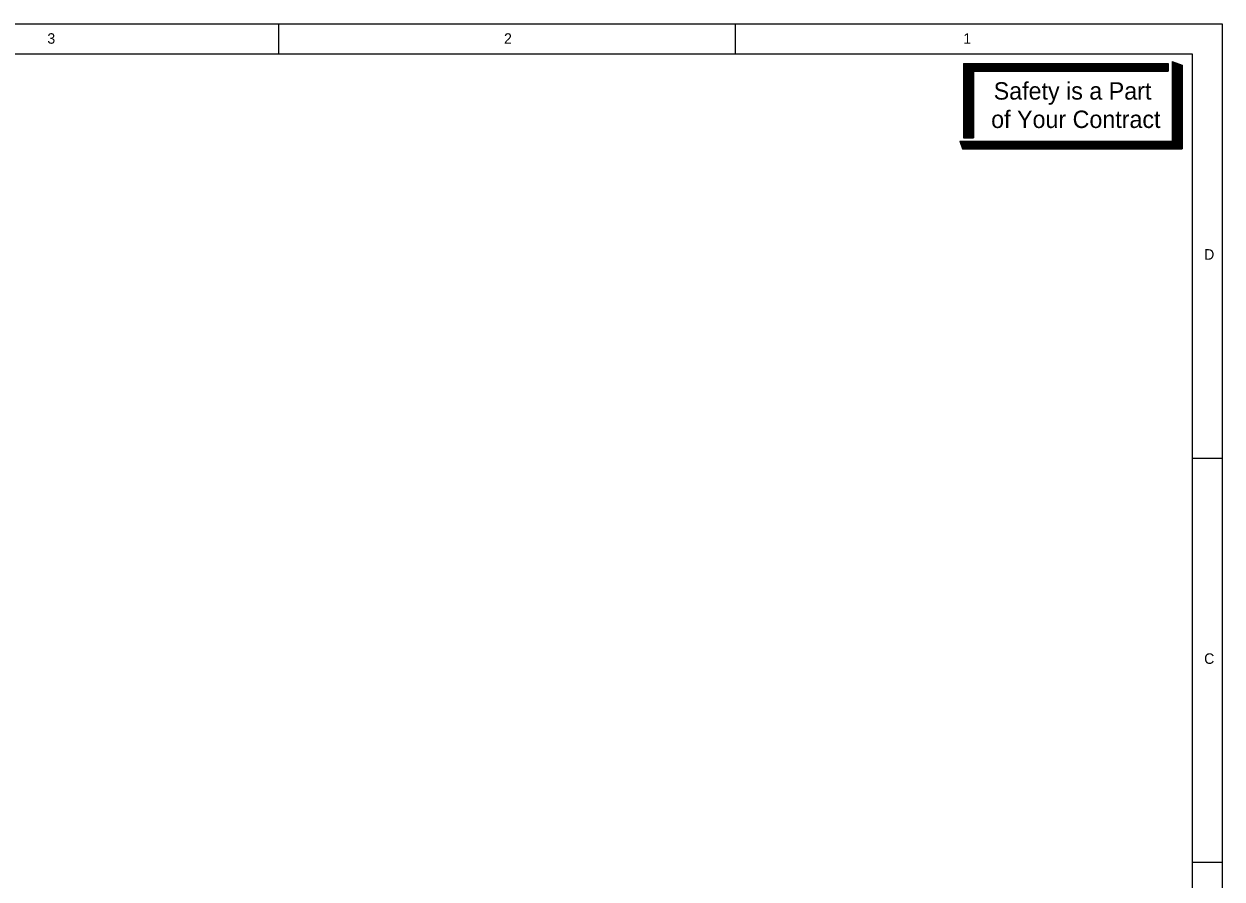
# Model space of a CAD drawing. Extents: x 0 to 320, y -4 to 473.
# Drawn here: x 280.44 to 320.45, y 444.86 to 473.42 of the extents above; entities that cross this region are included whole.
import ezdxf

# ---------------------------------------------------------------- set-up
doc = ezdxf.new("R2010")
doc.units = 0
doc.layers.add('Level 1', color=7, linetype='Continuous')

msp = doc.modelspace()

# ---------------------------------------------------------------- linework, layer by layer
at = {"layer": 'Level 1'}
for p, q in [((288.949, 472.416), (288.949, 473.416)), ((304.199, 472.416), (304.199, 473.416)), ((318.78, 472.164), (318.78, 469.496)), ((318.78, 472.164), (319.114, 472.04)), ((318.802, 472.156), (318.802, 469.246)), ((318.832, 472.144), (318.832, 469.246)), ((318.864, 472.132), (318.864, 469.246)), ((318.896, 472.12), (318.896, 469.246)), ((318.926, 472.11), (318.926, 469.246)), ((311.82, 472.09), (318.654, 472.09)), ((311.82, 472.09), (311.82, 469.608)), ((311.82, 472.058), (318.654, 472.058)), ((311.82, 472.028), (318.654, 472.028)), ((311.82, 471.996), (318.654, 471.996)), ((311.82, 471.964), (318.654, 471.964)), ((311.82, 471.934), (318.654, 471.934)), ((311.82, 471.902), (318.654, 471.902)), ((311.82, 471.872), (318.654, 471.872)), ((311.852, 472.09), (311.852, 469.608)), ((311.882, 472.09), (311.882, 469.608)), ((311.914, 472.09), (311.914, 469.608)), ((311.944, 472.09), (311.944, 469.608)), ((311.976, 472.09), (311.976, 469.608)), ((312.008, 472.09), (312.008, 469.608)), ((312.038, 472.09), (312.038, 469.608)), ((312.07, 472.09), (312.07, 469.608)), ((312.102, 472.09), (312.102, 469.608)), ((312.132, 472.09), (312.132, 469.608)), ((312.154, 471.84), (318.654, 471.84)), ((312.154, 471.84), (312.154, 469.608)), ((318.654, 472.09), (318.654, 471.84)), ((318.958, 472.098), (318.958, 469.246)), ((318.988, 472.086), (318.988, 469.246)), ((319.02, 472.074), (319.02, 469.246)), ((319.052, 472.064), (319.052, 469.246)), ((319.082, 472.04), (319.082, 469.246)), ((319.114, 472.04), (319.114, 469.246)), ((311.694, 469.496), (318.78, 469.496)), ((311.694, 469.496), (311.786, 469.246)), ((311.706, 469.464), (318.802, 469.464)), ((311.716, 469.434), (318.802, 469.434)), ((311.728, 469.402), (318.802, 469.402)), ((311.74, 469.37), (318.802, 469.37)), ((311.752, 469.34), (318.802, 469.34)), ((311.764, 469.308), (318.802, 469.308)), ((311.82, 469.608), (312.154, 469.608)), ((311.774, 469.278), (318.802, 469.278)), ((311.786, 469.246), (319.114, 469.246)), ((319.449, 458.916), (320.449, 458.916)), ((319.449, 445.416), (320.449, 445.416))]:
    msp.add_line(p, q, dxfattribs=at)
for points in [[(240.449, 473.416), (320.449, 473.416), (320.449, 417.416), (240.449, 417.416)], [(243.449, 472.416), (319.449, 472.416), (319.449, 418.416), (243.449, 418.416)]]:
    msp.add_lwpolyline(points, close=True, dxfattribs=at)

# ---------------------------------------------------------------- texts
for s, height, p in [('3', 0.351, (281.222, 472.755)), ('2', 0.351, (296.472, 472.754)), ('1', 0.351, (311.81, 472.754)), ('Safety is a Part', 0.58075, (312.823, 470.889)), ('of Your Contract', 0.58075, (312.739, 469.941)), ('D', 0.351, (319.851, 465.543)), ('C', 0.351, (319.851, 452.043))]:
    msp.add_text(s, height=height, dxfattribs=at).set_placement(p)

doc.saveas('drawing.dxf')
